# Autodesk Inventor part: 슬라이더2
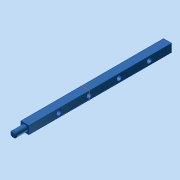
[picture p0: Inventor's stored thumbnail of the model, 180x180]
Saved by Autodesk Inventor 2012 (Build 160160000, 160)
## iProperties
Company: 한국ATC센터
Created: 2015-04
Part Number: 슬라이더2
Document SubType Name: Modeling
Designer: KYOUNG IL JANG
Density: 7.85 g/cm^3
Material: 강
Author: KYOUNG IL JANG
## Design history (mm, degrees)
sketch "스케치3"
  geometry: L1 (4, 142)-(-4, 142); L2 (-4, 142)-(-4, 0); L3 (-4, 0)-(4, 0); L4 (4, 0)-(4, 142); 3 further points
  constraints: 8 end point, 2 coincident, 2 parallel, 1 horizontal, 1 midpoint, 1 perpendicular
  dimensions: "d5" = 8 distance of L1.start L1.end; "d6" = 142 distance of L1.end L2.end
extrude "돌출3" new body sketch "스케치3" stored distance "d7" = 8; taper "d8" = 0 deg
sketch "스케치4"
  geometry: L1 (8, 0)-(0, 0) reference; 3 further points
  constraints: 1 midpoint, 1 vertical alignment
  dimensions: "d9" = 30 distance of point (4, 30) point (4, 0)
hole "구멍1" sketch "스케치4" at (4, 30) diameter "d10" = 5; stored, may be unused: countersink angle "d14" = 90 deg, drill point angle "d16" = 118 deg; dims "d11" = 6, "d12" = 4, "d13" = 2, "d15" = 8
sketch "스케치5"
  geometry: C1 r 3 at (4, -4); 1 further point
  constraints: 1 centre point, 1 coincident
  dimensions: "d20" = 6 diameter of C1
extrude "돌출4" join sketch "스케치5" distance "d21" = 12; taper "d22" = 0 deg
chamfer "모따기1" distance "d23" = 1; stored, may be unused: second distance "d24" = 2, angle "d25" = 45 deg
node "작업 평면2"
  node "작업축1"
node "솔리드1"
pattern_linear "직사각형 패턴1" dims "d19" = 30
node "솔리드2"
other parameters: "d26" = 0
